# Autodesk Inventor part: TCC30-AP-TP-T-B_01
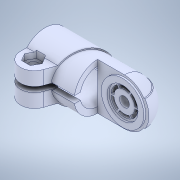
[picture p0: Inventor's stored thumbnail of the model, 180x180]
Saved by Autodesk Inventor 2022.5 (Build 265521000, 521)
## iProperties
Created: 2023-09
Part Number: TCC30-AP-TP-T-B_01
Material: 一般
Document SubType Name: Modeling
Designer: ImaoCorp
Density: 1 g/cm^3
Appearance: 既定
Author: ImaoCorp
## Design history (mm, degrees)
feature "TCC30-AP-TP-T-B_01"
node "ソリッド1"
